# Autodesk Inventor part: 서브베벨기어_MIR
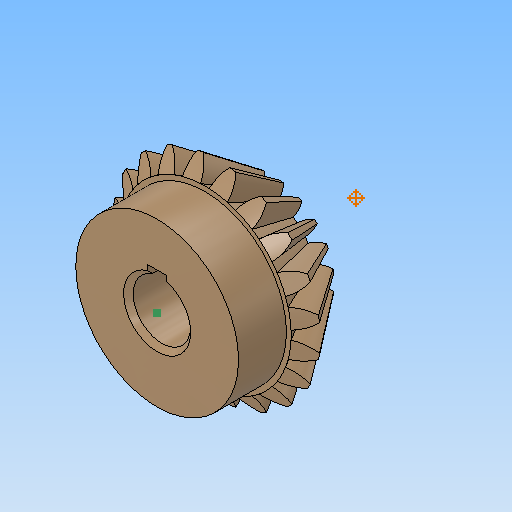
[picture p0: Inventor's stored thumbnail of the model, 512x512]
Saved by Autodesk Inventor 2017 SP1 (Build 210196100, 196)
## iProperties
Created: 2018-09
Part Number: 서브베벨기어_MIR
Material: 강철, 탄소
Document SubType Name: Modeling
Designer: MRC
Categories: <?xml version="1.0" encoding="UTF-16"?> <MemberInstance><Categories><FamilyTemplate><FamilyTemplateParameter ValueType="xs:double" Id="1" ObjectReferenceKey="da
Mass: 135.037 g
Surface Area: 63.6444 cm^2
Volume: 17.1585 cm^3
Density: 7.87 g/cm^3
Appearance: 반광택
d48: 0.000 mm
d49: 0.000 mm
d50: 90.00 deg
d52: 0.000 mm
d53: 0.000 mm
d54: 0.00 deg
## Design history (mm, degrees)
node "서브베벨기어"
  sketch "톱니 본체 스케치"
    geometry: L1 (0, 0)-(-18.003, -31.331) reference; L2 (-18.003, -31.331)-(-21.664, -28.891) reference; L3 (-21.664, -28.891)-(0, 0) reference; L4 (-20, -30)-(0, 0) reference; L5 (-10.813, -18.818)-(-13.012, -17.352) reference; L6 (-18.003, -31.331)-(-10.813, -18.818) reference; L7 (-21.664, -28.891)-(-13.012, -17.352) reference; L8 (0, -39.387)-(0, 6.564) reference; L9 (0, -30)-(-21.664, -30) reference
  sketch "시작 스케치"
    geometry: L1 (0, -23.505)-(0, 10.645) reference; L2 (0.834, -2.928)-(-0.834, -2.928) reference; A1 r 27.357 centre (0, -24.037) between (3.903, 3.04) and (-3.903, 3.04) reference; A2 r 8.898 centre (9.698, -3.713) between (3.903, 3.04) and (0.834, -2.928) reference; A3 r 8.898 centre (-9.698, -3.713) between (-0.834, -2.928) and (-3.903, 3.04) reference; 1 further point
  sketch "끝 스케치"
    geometry: L1 (0, -15.359)-(0, 6.983) reference; L2 (0.497, -1.72)-(-0.497, -1.72) reference; A1 r 16.291 centre (0, -14.29) between (2.324, 1.834) and (-2.324, 1.834) reference; A2 r 5.299 centre (5.775, -2.187) between (2.324, 1.834) and (0.497, -1.72) reference; A3 r 5.299 centre (-5.775, -2.187) between (-0.497, -1.72) and (-2.324, 1.834) reference; 1 further point
  sketch "끝 스케치 오른쪽"
    geometry: L1 (0, -22.649)-(0, 12.15) reference; L2 (0.497, -1.72)-(-0.497, -1.72) reference; A1 r 5.299 centre (5.775, -2.187) between (2.324, 1.834) and (0.497, -1.72) reference; A2 r 5.299 centre (-5.775, -2.187) between (-0.497, -1.72) and (-2.324, 1.834) reference; A3 r 16.291 centre (0, -14.29) between (2.324, 1.834) and (-2.324, 1.834) reference; 1 further point
  sketch "끝 스케치 왼쪽"
    geometry: L1 (0, -35.087)-(0, 18.089) reference; L2 (0.497, -1.716)-(-0.497, -1.716) reference; A1 r 16.291 centre (0, -14.287) between (2.324, 1.838) and (-2.324, 1.838) reference; A2 r 5.299 centre (5.775, -2.183) between (2.324, 1.838) and (0.497, -1.716) reference; A3 r 5.299 centre (-5.775, -2.183) between (-0.497, -1.716) and (-2.324, 1.838) reference; 2 further points; 1 other entity
    constraints: 1 other
  sketch "본체 스케치"
    geometry: L1 (0, -35.038)-(0, -19.531) reference; L2 (-18.003, -31.331)-(-10.813, -18.818) reference; L3 (-10.813, -18.818)-(0, -18.818) reference; L4 (-18.003, -31.331)-(0, -31.331) reference
  sketch "Sketch6"
    geometry: L1 (-20, -30)-(0, 0) reference; L2 (0, -37.8)-(0, 6.3) reference
  sketch "스케치8"
    geometry: C1 r 17 at (0, 0) reference; 1 further point
  sketch "스케치9"
    geometry: 1 further point
  sketch "스케치10"
    geometry: 1 further point
  sketch "스케치11"
    geometry: 1 further point
  sketch "스케치12"
    geometry: L1 (2, 5.657)-(2, 7.8) reference; L2 (2, 7.8)-(-2, 7.8) reference; L3 (-2, 7.8)-(-2, 5.657) reference; A1 r 6 centre (0, 0) between (2, 5.657) and (-2, 5.657) reference; 1 further point
  sketch "3D 스케치 오른쪽"
  sketch "3D 스케치 왼쪽"
  node "메쉬 평면"
  node "맨 위 평면"
  node "톱니 평면"
  node "끝 평면"
  node "끝 평면 왼쪽"
  node "메쉬 평면2"
  node "끝 평면 오른쪽"
  node "Z Axis_1"
  node "맨 위 점"
  node "시작점"
  node "끝점"
feature "Solid1::서브베벨기어"
tag "피쳐 태그1"
node "곡면1"
node "솔리드1"
feature "Srf1::파생"
other parameters: "d48" = 0, "d49" = 0, "d50" = 90 deg, "d52" = 0, "d53" = 0, "d54" = 0 deg
